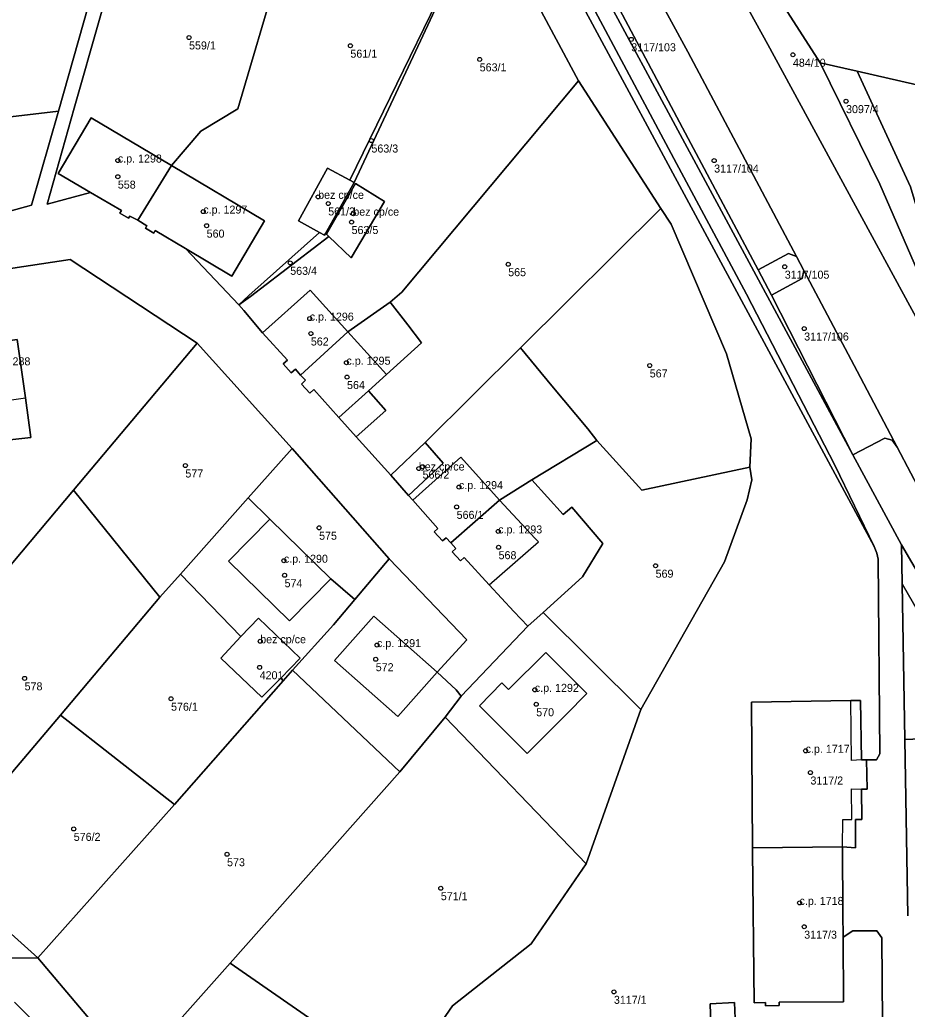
# Model space of a CAD drawing. Extents: x -878211 to -870363, y -1058464 to -1052522.
# Drawn here: x -874178.2 to -874067.3, y -1056644.7 to -1056521.1 of the extents above; entities that cross this region are included whole.
import ezdxf

# ---------------------------------------------------------------- set-up
doc = ezdxf.new("R2010")
doc.units = 0
for name, color, linetype in [('Definiční body', 7, 'Continuous'), ('Polygon budovy', 7, 'Continuous'), ('Polygon parcely', 7, 'Continuous')]:
    doc.layers.add(name, color=color, linetype=linetype)

msp = doc.modelspace()

# ---------------------------------------------------------------- linework, layer by layer
at = {"layer": 'Definiční body'}
for centre in [(-874157.09, -1056523.31994), (-874101.83, -1056523.54994), (-874136.93, -1056524.34994), (-874120.77, -1056526.05994), (-874081.63, -1056525.47994), (-874074.99, -1056531.27994), (-874134.3, -1056536.19994), (-874165.99, -1056538.68994), (-874091.47, -1056538.69994), (-874165.99, -1056540.70994), (-874140.96, -1056543.22994), (-874155.31, -1056545.06994), (-874139.7, -1056544.05994), (-874136.56, -1056545.32994), (-874154.89, -1056546.82994), (-874136.78, -1056546.37994), (-874144.45, -1056551.47994), (-874117.21, -1056551.64994), (-874082.65, -1056551.95994), (-874142.01, -1056558.43994), (-874080.22, -1056559.68994), (-874141.87, -1056560.30994), (-874137.42, -1056563.94994), (-874099.52, -1056564.29994), (-874137.35, -1056565.74994), (-874157.55, -1056576.79994), (-874128.38, -1056577.16994), (-874127.91, -1056576.93994), (-874123.36, -1056579.48994), (-874123.65, -1056581.96994), (-874140.84, -1056584.57994), (-874118.46, -1056585.02994), (-874118.41, -1056587.00994), (-874145.24, -1056588.68994), (-874098.79, -1056589.31994), (-874145.15, -1056590.50994), (-874148.2, -1056598.74994), (-874133.6, -1056599.22994), (-874133.76, -1056600.99994), (-874148.27, -1056602.00994), (-874177.64, -1056603.38994), (-874113.88, -1056604.81994), (-874159.34, -1056605.93994), (-874113.71, -1056606.62994), (-874080.04, -1056612.43994), (-874079.44, -1056615.15994), (-874171.5, -1056622.19994), (-874152.34, -1056625.36994), (-874125.63, -1056629.60994), (-874080.8, -1056631.43994), (-874080.22, -1056634.41994), (-874104, -1056642.55994)]:
    msp.add_circle(centre, 0.25, dxfattribs=at)
at = {"layer": 'Polygon budovy'}
for points in [[(-874173.44, -1056540.3), (-874169.41, -1056542.67), (-874165.54, -1056544.95), (-874165.72, -1056545.25), (-874164.67, -1056545.91), (-874164.48, -1056545.62), (-874163.5, -1056546.16), (-874159.27, -1056539.33), (-874169.33, -1056533.36)], [(-874159.27, -1056539.33), (-874163.5, -1056546.16), (-874162.35, -1056546.83), (-874162.53, -1056547.13), (-874161.49, -1056547.75), (-874161.31, -1056547.45), (-874157.54, -1056549.7), (-874151.73, -1056553.15), (-874147.66, -1056546.23)], [(-874143.43, -1056546.21), (-874140.8, -1056547.67), (-874140.16, -1056548.01), (-874140.03, -1056547.79), (-874136.47, -1056541.45), (-874137, -1056541.16), (-874139.77, -1056539.66)], [(-874139.61, -1056548.17), (-874136.83, -1056550.83), (-874132.68, -1056543.79), (-874136.31, -1056541.55), (-874139.93, -1056547.88)], [(-874141.97, -1056554.88), (-874147.92, -1056560.21), (-874144.8, -1056563.64), (-874145.32, -1056564.1), (-874144.33, -1056565.23), (-874143.8, -1056564.77), (-874143.18, -1056565.49), (-874137.24, -1056560.08)], [(-874143.18, -1056565.49), (-874142.52, -1056566.15), (-874143.03, -1056566.62), (-874142, -1056567.75), (-874141.48, -1056567.28), (-874138.37, -1056570.78), (-874134.65, -1056567.45), (-874132.42, -1056565.42), (-874137.24, -1056560.08)], [(-874178.59, -1056561.04), (-874189.11, -1056562.59), (-874188.01, -1056569.82), (-874177.51, -1056568.34)], [(-874127.6, -1056573.92), (-874131.89, -1056577.99), (-874129.65, -1056580.52), (-874125.34, -1056576.5)], [(-874129.12, -1056581.13), (-874125.99, -1056584.67), (-874126.44, -1056585.08), (-874125.4, -1056586.21), (-874124.97, -1056585.81), (-874124.39, -1056586.47), (-874118.29, -1056581.14), (-874123.12, -1056575.75)], [(-874124.2, -1056587.59), (-874123.18, -1056588.7), (-874122.72, -1056588.28), (-874119.57, -1056591.72), (-874113.43, -1056586.34), (-874113.83, -1056585.91), (-874118.29, -1056581.14), (-874124.39, -1056586.47), (-874123.75, -1056587.17)], [(-874144.55, -1056596.18), (-874139.36, -1056590.94), (-874146.98, -1056583.5), (-874152.15, -1056588.76)], [(-874153.11, -1056600.87), (-874148.01, -1056605.72), (-874145.64, -1056603.35), (-874143.19, -1056600.85), (-874148.43, -1056595.85), (-874150.64, -1056598.16)], [(-874134.01, -1056595.61), (-874138.93, -1056601.14), (-874131.02, -1056608.16), (-874126.08, -1056602.62)], [(-874120.78, -1056606.83), (-874119.91, -1056607.7), (-874114.82, -1056612.77), (-874109.98, -1056607.89), (-874107.4, -1056605.28), (-874112.5, -1056600.17), (-874117.15, -1056604.77), (-874118.01, -1056603.96)], [(-874074.41, -1056606.16), (-874086.8, -1056606.35), (-874086.66, -1056624.54), (-874075.44, -1056624.42), (-874075.38, -1056621.01), (-874074.28, -1056621), (-874074.31, -1056617.2), (-874073.04, -1056617.22), (-874072.36, -1056617.21), (-874072.43, -1056613.55), (-874073.04, -1056613.55), (-874074.32, -1056613.63)], [(-874086.66, -1056624.92), (-874086.47, -1056643.92), (-874085.05, -1056643.88), (-874085.04, -1056644.28), (-874083.36, -1056644.26), (-874083.36, -1056643.86), (-874075.31, -1056643.78), (-874075.36, -1056635.71), (-874075.38, -1056632.8), (-874075.44, -1056624.42), (-874086.66, -1056624.54)]]:
    msp.add_lwpolyline(points, close=True, dxfattribs=at)
at = {"layer": 'Polygon parcely'}
for points in [[(-873895.24, -1056850.14), (-873908.21, -1056824.62), (-873940.24, -1056755.07), (-873950.29, -1056741.89), (-873967.11, -1056720.96), (-873969.65, -1056722.8), (-873973.32, -1056718.02), (-874002.89, -1056678.66), (-874011.69, -1056666.89), (-874009.12, -1056664.87), (-874011.97, -1056661.51), (-874024.62, -1056638.91), (-874042.06, -1056605.74), (-874043.43, -1056601.67), (-874041.78, -1056601.01), (-874055.1, -1056577.75), (-874058.74, -1056569.35), (-874056.05, -1056577), (-874084.77, -1056524.21), (-874108.38, -1056481.4), (-874117.36, -1056461.73), (-874136.62, -1056429.22), (-874154.14, -1056399.02)], [(-874163.72, -1056410.72), (-874154.17, -1056427.16), (-874153.11, -1056428.98), (-874151.78, -1056431.47), (-874145.75, -1056434.35), (-874139.9, -1056444.4), (-874133.13, -1056456), (-874125.98, -1056468.28), (-874125.69, -1056468.78), (-874121.43, -1056476.25), (-874121.16, -1056476.73), (-874114.17, -1056489.53), (-874100.27, -1056514.97), (-874099.61, -1056516.18), (-874094.74, -1056525.1), (-874081.18, -1056550.68), (-874080.26, -1056552.41), (-874073.59, -1056565.01), (-874068.6, -1056574.52), (-874060.08, -1056590.74)], [(-874067.25, -1056633.06), (-874067.63, -1056611.01), (-874067.96, -1056591.56), (-874068.07, -1056586.7), (-874074.13, -1056575.46), (-874127.07, -1056477.21), (-874129.09, -1056473.51), (-874138.46, -1056458.61), (-874144.78, -1056447.71), (-874148.04, -1056438.4), (-874151.78, -1056431.47), (-874153.11, -1056428.98), (-874156.06, -1056430.01), (-874155.92, -1056430.26), (-874150.75, -1056439.85), (-874131.77, -1056475.08), (-874121.15, -1056492.86), (-874106.68, -1056519.41), (-874096.5, -1056538.44), (-874087.44, -1056555.37), (-874076.38, -1056576.74), (-874071.49, -1056586.91)], [(-874074.16, -1056634.92), (-874075.36, -1056635.71), (-874075.31, -1056643.78), (-874083.36, -1056643.86), (-874083.36, -1056644.26), (-874085.04, -1056644.28), (-874085.05, -1056643.88), (-874086.47, -1056643.92), (-874086.66, -1056624.92), (-874086.66, -1056624.54), (-874086.8, -1056606.35), (-874074.41, -1056606.16), (-874073.18, -1056606.14), (-874073.04, -1056613.55), (-874072.43, -1056613.55), (-874071.19, -1056613.58), (-874070.75, -1056612.82), (-874070.97, -1056588.48), (-874071.15, -1056587.74), (-874071.49, -1056586.91), (-874129.83, -1056478.68)], [(-874160.92, -1056488.32), (-874173.41, -1056532.51), (-874176.76, -1056544.26), (-874181.2, -1056545.49)], [(-874120.23, -1056506.71), (-874108.42, -1056528.72), (-874098.15, -1056544.68), (-874096.85, -1056546.64), (-874089.91, -1056562.82), (-874086.84, -1056573.44), (-874087.02, -1056577.02), (-874086.77, -1056578.58), (-874087.34, -1056581.09), (-874090.18, -1056588.83), (-874100.63, -1056607.28), (-874107.48, -1056626.55), (-874114.32, -1056636.54), (-874124.18, -1056644.32), (-874127.65, -1056649.36)], [(-874191.28, -1056553.95), (-874171.93, -1056551.04), (-874156.09, -1056561.49), (-874144.22, -1056574.68), (-874132.1, -1056588.45), (-874122.39, -1056598.58), (-874126.08, -1056602.62), (-874123.73, -1056604.82), (-874123.07, -1056605.62), (-874114.75, -1056596.85), (-874116.51, -1056595.05), (-874119.57, -1056591.72), (-874122.72, -1056588.28), (-874123.18, -1056588.7), (-874124.2, -1056587.59), (-874123.75, -1056587.17), (-874124.39, -1056586.47), (-874124.97, -1056585.81), (-874125.4, -1056586.21), (-874126.44, -1056585.08), (-874125.99, -1056584.67), (-874129.12, -1056581.13), (-874129.65, -1056580.52), (-874131.89, -1056577.99), (-874136.19, -1056573.21), (-874138.37, -1056570.78), (-874141.48, -1056567.28), (-874142, -1056567.75), (-874143.03, -1056566.62), (-874142.52, -1056566.15), (-874143.18, -1056565.49), (-874143.8, -1056564.77), (-874144.33, -1056565.23), (-874145.32, -1056564.1), (-874144.8, -1056563.64), (-874147.92, -1056560.21), (-874150.26, -1056557.43), (-874150.85, -1056556.73), (-874157.54, -1056549.7), (-874161.31, -1056547.45), (-874161.49, -1056547.75), (-874162.53, -1056547.13), (-874162.35, -1056546.83), (-874163.5, -1056546.16), (-874164.48, -1056545.62), (-874164.67, -1056545.91), (-874165.72, -1056545.25), (-874165.54, -1056544.95), (-874169.41, -1056542.67), (-874174.84, -1056544.14), (-874171.43, -1056532.16), (-874165.02, -1056509.6)], [(-874071.49, -1056586.91), (-874071.15, -1056587.74), (-874070.97, -1056588.48), (-874070.75, -1056612.82), (-874071.19, -1056613.58), (-874072.43, -1056613.55), (-874072.36, -1056617.21), (-874073.04, -1056617.22), (-874073, -1056621.04), (-874073.79, -1056621.04), (-874073.8, -1056624.58), (-874075.44, -1056624.42), (-874075.38, -1056632.8), (-874075.36, -1056635.71), (-874074.16, -1056634.92), (-874071.16, -1056634.92), (-874070.51, -1056635.8), (-874070.41, -1056651.6)], [(-874064.59, -1056610.89), (-874067.63, -1056611.01), (-874067.25, -1056633.06)], [(-874070.41, -1056651.6), (-874070.51, -1056635.8), (-874071.16, -1056634.92), (-874074.16, -1056634.92)], [(-874164.01, -1056652.5), (-874175.98, -1056638.3), (-874181.37, -1056638.36)], [(-874174.95, -1056647.79), (-874178.91, -1056643.85)], [(-874178.91, -1056643.85), (-874174.95, -1056647.79)], [(-874091.81, -1056649.22), (-874091.99, -1056644.04), (-874088.93, -1056643.88), (-874088.71, -1056648.87)], [(-874088.71, -1056648.87), (-874088.93, -1056643.88), (-874091.99, -1056644.04), (-874091.81, -1056649.22)]]:
    msp.add_lwpolyline(points, dxfattribs=at)
for points in [[(-874097.18, -1056496.94), (-874106.82, -1056479.54), (-874117.36, -1056461.73), (-874108.38, -1056481.4), (-874084.77, -1056524.21), (-874056.05, -1056577), (-874058.74, -1056569.35), (-874070.76, -1056541.63), (-874078.23, -1056526.48)], [(-874131.77, -1056475.08), (-874129.83, -1056478.68), (-874071.49, -1056586.91), (-874076.38, -1056576.74), (-874087.44, -1056555.37), (-874096.5, -1056538.44), (-874106.68, -1056519.41), (-874121.15, -1056492.86)], [(-874085.98, -1056552.34), (-874094.7, -1056535.93), (-874103.63, -1056519.14), (-874105.05, -1056516.61), (-874118.15, -1056492.49), (-874127.07, -1056477.21), (-874074.13, -1056575.46), (-874084.3, -1056555.51)], [(-874149.6, -1056555.55), (-874140.8, -1056547.67), (-874143.43, -1056546.21), (-874139.77, -1056539.66), (-874137, -1056541.16), (-874120.23, -1056506.71), (-874128.46, -1056498.19), (-874137.32, -1056485.56), (-874145.95, -1056515.13), (-874151.01, -1056532.24), (-874155.61, -1056535.02), (-874159.27, -1056539.33), (-874147.66, -1056546.23), (-874151.73, -1056553.15), (-874157.54, -1056549.7), (-874150.85, -1056556.73)], [(-874190.09, -1056529.9), (-874183.71, -1056528.93), (-874183, -1056533.63), (-874173.41, -1056532.51), (-874160.92, -1056488.32), (-874182.09, -1056489.79), (-874182.44, -1056494.26), (-874189.66, -1056527.88)], [(-874069.52, -1056495.93), (-874072.34, -1056497.46), (-874077.27, -1056499.42), (-874078.64, -1056495.93), (-874080.77, -1056490.34), (-874082.65, -1056491.07), (-874083.83, -1056488.11), (-874097.18, -1056496.94), (-874078.23, -1056526.48), (-874073.61, -1056527.53), (-874058.67, -1056530.92), (-874058.03, -1056527.95), (-874059.02, -1056523.78)], [(-874147.92, -1056560.21), (-874141.97, -1056554.88), (-874137.24, -1056560.08), (-874131.94, -1056556.38), (-874130.5, -1056555.14), (-874108.42, -1056528.72), (-874120.23, -1056506.71), (-874136.47, -1056541.45), (-874140.03, -1056547.79), (-874139.93, -1056547.88), (-874136.31, -1056541.55), (-874132.68, -1056543.79), (-874136.83, -1056550.83), (-874139.61, -1056548.17), (-874149.43, -1056555.67), (-874150.85, -1056556.73), (-874150.26, -1056557.43)], [(-874120.23, -1056506.71), (-874137, -1056541.16), (-874136.47, -1056541.45)], [(-874169.41, -1056542.67), (-874173.44, -1056540.3), (-874169.33, -1056533.36), (-874159.27, -1056539.33), (-874155.61, -1056535.02), (-874151.01, -1056532.24), (-874145.95, -1056515.13), (-874165.02, -1056509.6), (-874171.43, -1056532.16), (-874174.84, -1056544.14)], [(-874085.98, -1056552.34), (-874082.16, -1056550.32), (-874081.18, -1056550.68), (-874094.74, -1056525.1), (-874099.61, -1056516.18), (-874099.9, -1056517.21), (-874103.63, -1056519.14), (-874094.7, -1056535.93)], [(-874078.23, -1056526.48), (-874070.76, -1056541.63), (-874058.74, -1056569.35), (-874066.94, -1056541.99), (-874073.61, -1056527.53)], [(-874058.74, -1056569.35), (-874055.1, -1056577.75), (-874041.78, -1056601.01), (-874035.4, -1056613.17), (-874011.89, -1056655.9), (-873946.72, -1056739.16), (-873936.35, -1056752.76), (-873920.07, -1056788.11), (-873930.75, -1056761.9), (-873935.01, -1056752.39), (-873943.35, -1056736.97), (-873975.84, -1056699.09), (-874011.45, -1056652.11), (-874019.42, -1056638.08), (-874041.25, -1056593.06), (-874035.88, -1056579.88), (-874056.84, -1056534.05), (-874058.67, -1056530.92), (-874073.61, -1056527.53), (-874066.94, -1056541.99)], [(-874136.19, -1056573.21), (-874131.89, -1056577.99), (-874127.6, -1056573.92), (-874115.68, -1056562.08), (-874098.15, -1056544.68), (-874108.42, -1056528.72), (-874130.5, -1056555.14), (-874131.94, -1056556.38), (-874129.77, -1056559.23), (-874128.04, -1056561.46), (-874132.42, -1056565.42), (-874134.65, -1056567.45), (-874132.52, -1056569.91)], [(-874190.94, -1056530.05), (-874189.65, -1056538.6), (-874188.34, -1056546.72), (-874181.2, -1056545.49), (-874176.76, -1056544.26), (-874173.41, -1056532.51), (-874183, -1056533.63), (-874183.71, -1056528.93), (-874190.09, -1056529.9)], [(-874164.67, -1056545.91), (-874164.48, -1056545.62), (-874163.5, -1056546.16), (-874159.27, -1056539.33), (-874169.33, -1056533.36), (-874173.44, -1056540.3), (-874169.41, -1056542.67), (-874165.54, -1056544.95), (-874165.72, -1056545.25)], [(-874161.31, -1056547.45), (-874157.54, -1056549.7), (-874151.73, -1056553.15), (-874147.66, -1056546.23), (-874159.27, -1056539.33), (-874163.5, -1056546.16), (-874162.35, -1056546.83), (-874162.53, -1056547.13), (-874161.49, -1056547.75)], [(-874140.03, -1056547.79), (-874136.47, -1056541.45), (-874137, -1056541.16), (-874139.77, -1056539.66), (-874143.43, -1056546.21), (-874140.8, -1056547.67), (-874140.16, -1056548.01)], [(-874139.93, -1056547.88), (-874139.61, -1056548.17), (-874136.83, -1056550.83), (-874132.68, -1056543.79), (-874136.31, -1056541.55)], [(-874106.12, -1056573.67), (-874100.49, -1056579.86), (-874087.02, -1056577.02), (-874086.84, -1056573.44), (-874089.91, -1056562.82), (-874096.85, -1056546.64), (-874098.15, -1056544.68), (-874115.68, -1056562.08), (-874111.74, -1056566.83), (-874107.27, -1056572.19)], [(-874140.16, -1056548.01), (-874140.8, -1056547.67), (-874149.6, -1056555.55), (-874150.85, -1056556.73), (-874149.43, -1056555.67), (-874139.61, -1056548.17), (-874139.93, -1056547.88), (-874140.03, -1056547.79)], [(-874194.08, -1056575.2), (-874193.8, -1056576.98), (-874191.06, -1056594.52), (-874186.94, -1056598.2), (-874171.53, -1056579.86), (-874156.09, -1056561.49), (-874171.93, -1056551.04), (-874191.28, -1056553.95), (-874189.97, -1056562.75), (-874189.11, -1056562.59), (-874178.59, -1056561.04), (-874177.51, -1056568.34), (-874176.87, -1056573.3)], [(-874080.26, -1056552.41), (-874081.18, -1056550.68), (-874082.16, -1056550.32), (-874085.98, -1056552.34), (-874084.3, -1056555.51), (-874080.47, -1056553.44)], [(-874068.6, -1056574.52), (-874073.59, -1056565.01), (-874080.26, -1056552.41), (-874080.47, -1056553.44), (-874084.3, -1056555.51), (-874074.13, -1056575.46), (-874070.16, -1056573.37), (-874069.22, -1056573.64)], [(-874177.51, -1056568.34), (-874178.59, -1056561.04), (-874189.11, -1056562.59), (-874189.97, -1056562.75), (-874191.28, -1056553.95), (-874197.51, -1056554.9), (-874197.34, -1056555.57), (-874196.34, -1056561.62), (-874195.86, -1056563.71), (-874194.6, -1056572.5), (-874194.08, -1056575.2), (-874176.87, -1056573.3)], [(-874144.33, -1056565.23), (-874143.8, -1056564.77), (-874143.18, -1056565.49), (-874137.24, -1056560.08), (-874141.97, -1056554.88), (-874147.92, -1056560.21), (-874144.8, -1056563.64), (-874145.32, -1056564.1)], [(-874132.52, -1056569.91), (-874134.65, -1056567.45), (-874132.42, -1056565.42), (-874128.04, -1056561.46), (-874129.77, -1056559.23), (-874131.94, -1056556.38), (-874137.24, -1056560.08), (-874143.18, -1056565.49), (-874142.52, -1056566.15), (-874143.03, -1056566.62), (-874142, -1056567.75), (-874141.48, -1056567.28), (-874138.37, -1056570.78), (-874136.19, -1056573.21)], [(-874171.53, -1056579.86), (-874160.76, -1056593.24), (-874158.17, -1056590.35), (-874149.7, -1056580.83), (-874144.22, -1056574.68), (-874156.09, -1056561.49)], [(-874125.34, -1056576.5), (-874129.65, -1056580.52), (-874129.12, -1056581.13), (-874125.99, -1056584.67), (-874126.44, -1056585.08), (-874125.4, -1056586.21), (-874124.97, -1056585.81), (-874124.39, -1056586.47), (-874118.29, -1056581.14), (-874114.26, -1056578.58), (-874106.12, -1056573.67), (-874107.27, -1056572.19), (-874111.74, -1056566.83), (-874115.68, -1056562.08), (-874127.6, -1056573.92)], [(-874127.6, -1056573.92), (-874131.89, -1056577.99), (-874129.65, -1056580.52), (-874125.34, -1056576.5)], [(-874114.26, -1056578.58), (-874110.34, -1056582.92), (-874109.25, -1056582), (-874105.37, -1056586.52), (-874107.94, -1056590.7), (-874112.84, -1056595.16), (-874100.63, -1056607.28), (-874090.18, -1056588.83), (-874087.34, -1056581.09), (-874086.77, -1056578.58), (-874087.02, -1056577.02), (-874100.49, -1056579.86), (-874106.12, -1056573.67)], [(-874074.13, -1056575.46), (-874068.07, -1056586.7), (-874056.86, -1056605.84), (-874056.32, -1056604.38), (-874055.95, -1056602.39), (-874056.61, -1056598.06), (-874060.08, -1056590.74), (-874068.6, -1056574.52), (-874069.22, -1056573.64), (-874070.16, -1056573.37)], [(-874144.22, -1056574.68), (-874149.7, -1056580.83), (-874146.98, -1056583.5), (-874139.36, -1056590.94), (-874136.38, -1056593.54), (-874132.1, -1056588.45)], [(-874119.57, -1056591.72), (-874116.51, -1056595.05), (-874114.75, -1056596.85), (-874112.84, -1056595.16), (-874107.94, -1056590.7), (-874105.37, -1056586.52), (-874109.25, -1056582), (-874110.34, -1056582.92), (-874114.26, -1056578.58), (-874118.29, -1056581.14), (-874124.39, -1056586.47), (-874123.75, -1056587.17), (-874124.2, -1056587.59), (-874123.18, -1056588.7), (-874122.72, -1056588.28)], [(-874186.94, -1056598.2), (-874203.32, -1056616.78), (-874188.99, -1056626.63), (-874173.15, -1056607.98), (-874160.76, -1056593.24), (-874171.53, -1056579.86)], [(-874148.43, -1056595.85), (-874143.19, -1056600.85), (-874145.64, -1056603.35), (-874145.32, -1056603.68), (-874144.17, -1056602.36), (-874139.02, -1056596.68), (-874136.38, -1056593.54), (-874139.36, -1056590.94), (-874146.98, -1056583.5), (-874149.7, -1056580.83), (-874158.17, -1056590.35), (-874150.64, -1056598.16)], [(-874067.96, -1056591.56), (-874058.41, -1056608.19), (-874057.58, -1056607.18), (-874056.86, -1056605.84), (-874068.07, -1056586.7)], [(-874139.02, -1056596.68), (-874144.17, -1056602.36), (-874130.75, -1056615.06), (-874125.1, -1056608.23), (-874123.07, -1056605.62), (-874123.73, -1056604.82), (-874126.08, -1056602.62), (-874122.39, -1056598.58), (-874132.1, -1056588.45), (-874136.38, -1056593.54)], [(-874153.11, -1056600.87), (-874150.64, -1056598.16), (-874158.17, -1056590.35), (-874160.76, -1056593.24), (-874173.15, -1056607.98), (-874158.92, -1056619.13), (-874145.32, -1056603.68), (-874145.64, -1056603.35), (-874148.01, -1056605.72)], [(-874067.63, -1056611.01), (-874064.59, -1056610.89), (-874062.54, -1056610.49), (-874060.2, -1056609.55), (-874058.41, -1056608.19), (-874067.96, -1056591.56)], [(-874123.07, -1056605.62), (-874125.1, -1056608.23), (-874107.48, -1056626.55), (-874100.63, -1056607.28), (-874112.84, -1056595.16), (-874114.75, -1056596.85)], [(-874145.64, -1056603.35), (-874143.19, -1056600.85), (-874148.43, -1056595.85), (-874150.64, -1056598.16), (-874153.11, -1056600.87), (-874148.01, -1056605.72)], [(-874130.75, -1056615.06), (-874144.17, -1056602.36), (-874145.32, -1056603.68), (-874158.92, -1056619.13), (-874175.98, -1056638.3), (-874164.01, -1056652.5), (-874151.96, -1056638.95)], [(-874208.22, -1056614.01), (-874231.19, -1056604.99), (-874239.69, -1056603.56), (-874238.72, -1056603.94), (-874223.65, -1056609.94), (-874216.83, -1056612.72), (-874213.39, -1056614.34), (-874209.62, -1056616.27), (-874206.06, -1056618.49), (-874203.1, -1056620.54), (-874197.8, -1056624.55), (-874191.74, -1056629.29), (-874186.9, -1056633.38), (-874181.37, -1056638.36), (-874175.98, -1056638.3), (-874188.99, -1056626.63), (-874203.32, -1056616.78)], [(-874072.36, -1056617.21), (-874072.43, -1056613.55), (-874073.04, -1056613.55), (-874073.18, -1056606.14), (-874074.41, -1056606.16), (-874086.8, -1056606.35), (-874086.66, -1056624.54), (-874075.44, -1056624.42), (-874073.8, -1056624.58), (-874073.79, -1056621.04), (-874073, -1056621.04), (-874073.04, -1056617.22)], [(-874158.92, -1056619.13), (-874173.15, -1056607.98), (-874188.99, -1056626.63), (-874175.98, -1056638.3)], [(-874151.96, -1056638.95), (-874129.25, -1056654.72), (-874127.65, -1056649.36), (-874124.18, -1056644.32), (-874114.32, -1056636.54), (-874107.48, -1056626.55), (-874125.1, -1056608.23), (-874130.75, -1056615.06)], [(-874075.36, -1056635.71), (-874075.38, -1056632.8), (-874075.44, -1056624.42), (-874086.66, -1056624.54), (-874086.66, -1056624.92), (-874086.47, -1056643.92), (-874085.05, -1056643.88), (-874085.04, -1056644.28), (-874083.36, -1056644.26), (-874083.36, -1056643.86), (-874075.31, -1056643.78)], [(-874157.85, -1056661.91), (-874151.72, -1056669.25), (-874147.35, -1056673.9), (-874141.03, -1056681.42), (-874138.18, -1056679.67), (-874135.77, -1056677.69), (-874133.84, -1056675.3), (-874132.05, -1056672.51), (-874130.98, -1056669.84), (-874130.03, -1056666.85), (-874129.25, -1056654.72), (-874151.96, -1056638.95), (-874164.01, -1056652.5)]]:
    msp.add_lwpolyline(points, close=True, dxfattribs=at)

# ---------------------------------------------------------------- texts
at = {"layer": 'Definiční body'}
for s, p in [('559/1', (-874157.09, -1056524.809)), ('561/1', (-874136.93, -1056525.839)), ('3117/103', (-874101.83, -1056525.039)), ('484/10', (-874081.63, -1056526.969)), ('563/1', (-874120.77, -1056527.549)), ('3097/4', (-874074.99, -1056532.769)), ('563/3', (-874134.3, -1056537.689)), ('c.p. 1298', (-874165.99, -1056538.94)), ('3117/104', (-874091.47, -1056540.189)), ('558', (-874165.99, -1056542.199)), ('bez cp/ce', (-874140.96, -1056543.48)), ('c.p. 1297', (-874155.31, -1056545.32)), ('561/3', (-874139.7, -1056545.549)), ('bez cp/ce', (-874136.56, -1056545.58)), ('560', (-874154.89, -1056548.319)), ('563/5', (-874136.78, -1056547.869)), ('563/4', (-874144.45, -1056552.969)), ('565', (-874117.21, -1056553.139)), ('3117/105', (-874082.65, -1056553.449)), ('c.p. 1296', (-874142.01, -1056558.69)), ('562', (-874141.87, -1056561.799)), ('3117/106', (-874080.22, -1056561.179)), ('c.p. 1288', (-874182.42, -1056564.28)), ('c.p. 1295', (-874137.42, -1056564.2)), ('567', (-874099.52, -1056565.789)), ('564', (-874137.35, -1056567.239)), ('bez cp/ce', (-874128.38, -1056577.419)), ('577', (-874157.55, -1056578.289)), ('566/2', (-874127.91, -1056578.429)), ('c.p. 1294', (-874123.36, -1056579.74)), ('566/1', (-874123.65, -1056583.459)), ('c.p. 1293', (-874118.46, -1056585.28)), ('575', (-874140.84, -1056586.069)), ('c.p. 1290', (-874145.24, -1056588.94)), ('568', (-874118.41, -1056588.499)), ('569', (-874098.79, -1056590.809)), ('574', (-874145.15, -1056591.999)), ('bez cp/ce', (-874148.2, -1056599)), ('c.p. 1291', (-874133.6, -1056599.48)), ('572', (-874133.76, -1056602.489)), ('4201', (-874148.27, -1056603.499)), ('578', (-874177.64, -1056604.879)), ('c.p. 1292', (-874113.88, -1056605.07)), ('576/1', (-874159.34, -1056607.429)), ('570', (-874113.71, -1056608.119)), ('c.p. 1717', (-874080.04, -1056612.69)), ('3117/2', (-874079.44, -1056616.649)), ('576/2', (-874171.5, -1056623.689)), ('573', (-874152.34, -1056626.859)), ('571/1', (-874125.63, -1056631.099)), ('c.p. 1718', (-874080.8, -1056631.69)), ('3117/3', (-874080.22, -1056635.909)), ('3117/1', (-874104, -1056644.049))]:
    msp.add_text(s, height=0.999996, dxfattribs=at).set_placement(p)

doc.saveas('drawing.dxf')
